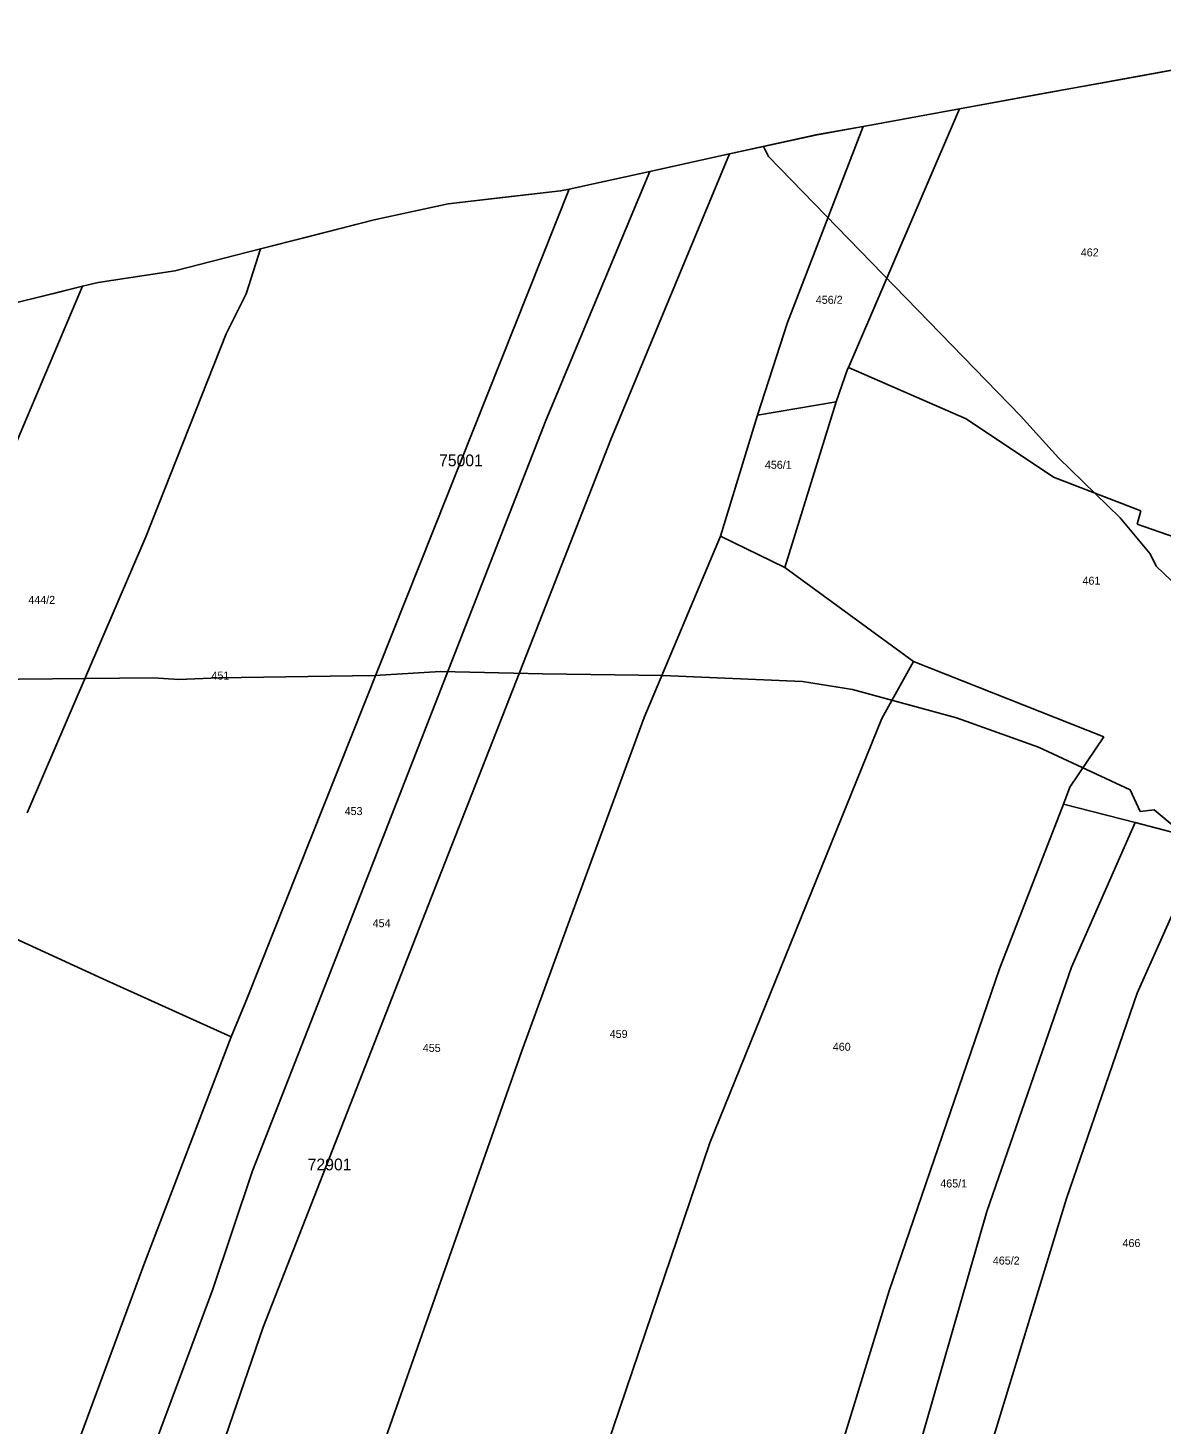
# Model space of a CAD drawing. Extents: x -743888 to -742027, y -1128394 to -1126768.
# Drawn here: x -742998.7 to -742758.2, y -1127090.1 to -1126793.6 of the extents above; entities that cross this region are included whole.
import ezdxf

# ---------------------------------------------------------------- set-up
doc = ezdxf.new("R2010")
doc.units = 0
for name, color, linetype in [('Vrstva 13', 7, 'Continuous'), ('Vrstva 18', 7, 'Continuous'), ('Vrstva 52', 7, 'Continuous'), ('Vrstva 53', 7, 'Continuous'), ('Vrstva 6', 7, 'Continuous')]:
    doc.layers.add(name, color=color, linetype=linetype)

msp = doc.modelspace()

# ---------------------------------------------------------------- linework, layer by layer
at = {"layer": 'Vrstva 13'}
for points in [[(-742769.01, -1126804.93), (-742735.24, -1126798.77)], [(-742800.98, -1126810.76), (-742782.52, -1126807.39)], [(-742782.52, -1126807.39), (-742769.01, -1126804.93)], [(-742821.45, -1126814.49), (-742800.98, -1126810.76)], [(-742849.79, -1126820.34), (-742831.12, -1126816.25)], [(-742831.12, -1126816.25), (-742821.45, -1126814.49)], [(-742859.97, -1126822.57), (-742849.79, -1126820.34)], [(-742883.83, -1126827.8), (-742866.72, -1126824.05)], [(-742866.72, -1126824.05), (-742859.97, -1126822.57)], [(-742897.44, -1126829.55), (-742885.68, -1126828.21)], [(-742885.68, -1126828.21), (-742883.83, -1126827.8)], [(-742925.21, -1126834.34), (-742909.52, -1126830.92)], [(-742909.52, -1126830.92), (-742897.44, -1126829.55)], [(-742939.84, -1126838.09), (-742925.21, -1126834.34)], [(-742949.34, -1126840.52), (-742939.84, -1126838.09)], [(-742967.54, -1126845.19), (-742949.34, -1126840.52)], [(-742983.82, -1126847.62), (-742967.54, -1126845.19)], [(-742992.38, -1126849.75), (-742987.15, -1126848.45)], [(-742987.15, -1126848.45), (-742983.82, -1126847.62)], [(-743014.97, -1126855.23), (-742997.62, -1126851.06)], [(-742997.62, -1126851.06), (-742992.38, -1126849.75)]]:
    msp.add_lwpolyline(points, dxfattribs=at)
at = {"layer": 'Vrstva 52'}
for points in [[(-742842.63, -1126818.77), (-742831.23, -1126816.27), (-742821.45, -1126814.49), (-742800.98, -1126810.76), (-742706.72, -1126793.58)], [(-743014.97, -1126855.23), (-742997.62, -1126851.06), (-742987.15, -1126848.45), (-742983.82, -1126847.62), (-742967.54, -1126845.19), (-742949.34, -1126840.52), (-742925.21, -1126834.34), (-742909.52, -1126830.92), (-742885.68, -1126828.21), (-742883.83, -1126827.8), (-742866.72, -1126824.05), (-742849.79, -1126820.34), (-742842.63, -1126818.77)], [(-742842.63, -1126818.77), (-742841.5, -1126820.88), (-742788.06, -1126876), (-742780, -1126884.88), (-742766.88, -1126897.63), (-742760.5, -1126905.25), (-742759.25, -1126907.88), (-742728.25, -1126937.5)], [(-743062.18, -1126930.43), (-743007.81, -1126932), (-742972.19, -1126931.63), (-742966.69, -1126932), (-742958.19, -1126931.63), (-742925.13, -1126931.13), (-742911.13, -1126930.25), (-742889.44, -1126930.75), (-742864, -1126931.13), (-742834.31, -1126932.38), (-742823.69, -1126934.13), (-742801.63, -1126940.13), (-742784.25, -1126946.38), (-742764.75, -1126955.38), (-742762.63, -1126960), (-742759.63, -1126959.63), (-742751.19, -1126966.75), (-742748.56, -1126970.88), (-742745.84, -1126975.32)]]:
    msp.add_lwpolyline(points, dxfattribs=at)
at = {"layer": 'Vrstva 6'}
for points in [[(-742824.58, -1126865.74), (-742800.98, -1126810.76)], [(-742837.53, -1126856.16), (-742821.45, -1126814.49)], [(-742875.03, -1126881.03), (-742849.79, -1126820.34)], [(-742888.83, -1126876.94), (-742866.72, -1126824.05)], [(-742933.06, -1126951.45), (-742883.83, -1126827.8)], [(-742952.43, -1126850.05), (-742949.34, -1126840.52)], [(-743003.48, -1126887.11), (-742987.15, -1126848.45)], [(-742956.68, -1126858.57), (-742952.43, -1126850.05)], [(-742843.85, -1126875.84), (-742837.53, -1126856.16)], [(-742973.7, -1126901.64), (-742956.68, -1126858.57)], [(-742827.15, -1126873), (-742824.73, -1126866.08)], [(-742824.73, -1126866.08), (-742824.58, -1126865.74)], [(-742824.58, -1126865.74), (-742799.57, -1126876.62)], [(-742843.85, -1126875.84), (-742827.15, -1126873)], [(-742838.1, -1126908.15), (-742827.15, -1126873)], [(-742935.17, -1126995.67), (-742888.83, -1126876.94)], [(-742851.71, -1126901.51), (-742843.85, -1126875.84)], [(-742799.57, -1126876.62), (-742781.04, -1126889)], [(-742891.52, -1126923.09), (-742875.03, -1126881.03)], [(-742781.04, -1126889), (-742762.5, -1126896.14)], [(-742763.27, -1126898.97), (-742762.5, -1126896.14)], [(-742763.27, -1126898.97), (-742750.49, -1126903.46)], [(-742998.88, -1126960.31), (-742973.7, -1126901.64)], [(-742867.91, -1126940.04), (-742851.71, -1126901.51)], [(-742851.71, -1126901.51), (-742838.1, -1126908.15)], [(-742838.1, -1126908.15), (-742810.76, -1126928.12)], [(-742913.81, -1126980), (-742891.52, -1126923.09)], [(-742817.51, -1126940.24), (-742810.76, -1126928.12)], [(-742810.76, -1126928.12), (-742770.36, -1126944.15)], [(-742884.2, -1126984.32), (-742867.91, -1126940.04)], [(-742854.01, -1127030.4), (-742817.51, -1126940.24)], [(-742777.55, -1126954.82), (-742770.36, -1126944.15)], [(-742952.5, -1127000.35), (-742933.06, -1126951.45)], [(-742778.92, -1126958.45), (-742777.55, -1126954.82)], [(-742792.49, -1126993.43), (-742778.92, -1126958.45)], [(-742778.92, -1126958.45), (-742763.72, -1126962.33)], [(-742777.21, -1126993.06), (-742763.72, -1126962.33)], [(-742763.72, -1126962.33), (-742748.81, -1126966.24)], [(-742763.25, -1126998.63), (-742748.81, -1126966.24)], [(-742948.78, -1127069.51), (-742913.81, -1126980)], [(-743011.05, -1126982.56), (-742982.82, -1126995.58)], [(-742894, -1127011.08), (-742884.2, -1126984.32)], [(-742815.95, -1127061.82), (-742792.49, -1126993.43)], [(-742795.18, -1127045), (-742777.21, -1126993.06)], [(-742982.82, -1126995.58), (-742955.58, -1127007.86)], [(-742951.08, -1127036.33), (-742935.17, -1126995.67)], [(-742778.25, -1127042.21), (-742763.25, -1126998.63)], [(-742955.58, -1127007.86), (-742952.5, -1127000.35)], [(-742973.91, -1127055.72), (-742955.58, -1127007.86)], [(-742935.81, -1127130.03), (-742894, -1127011.08)], [(-742891, -1127139.53), (-742854.01, -1127030.4)], [(-742959.53, -1127061.71), (-742951.08, -1127036.33)], [(-742813.25, -1127156.61), (-742778.25, -1127042.21)], [(-742812.1, -1127103.89), (-742795.18, -1127045)], [(-742988.72, -1127095.72), (-742973.91, -1127055.72)], [(-742981.52, -1127120.42), (-742959.53, -1127061.71)], [(-742842.98, -1127149.74), (-742815.95, -1127061.82)], [(-742967.31, -1127123.32), (-742948.78, -1127069.51)]]:
    msp.add_lwpolyline(points, dxfattribs=at)

# ---------------------------------------------------------------- texts
at = {"layer": 'Vrstva 18'}
for s, p in [('462', (-742775.24, -1126842.11)), ('456/2', (-742831.49, -1126852.18)), ('456/1', (-742842.3, -1126887.22)), ('461', (-742774.87, -1126911.83)), ('444/2', (-742998.66, -1126915.91)), ('451', (-742959.78, -1126931.98)), ('453', (-742931.51, -1126960.77)), ('454', (-742925.56, -1126984.58)), ('459', (-742875.24, -1127008.1)), ('460', (-742827.88, -1127010.83)), ('455', (-742914.92, -1127011.08)), ('465/1', (-742805.07, -1127039.87)), ('466', (-742766.38, -1127052.52)), ('465/2', (-742793.91, -1127056.24))]:
    msp.add_text(s, height=1.7, dxfattribs=at).set_placement(p)
at = {"layer": 'Vrstva 53'}
for s, p in [('75001', (-742911.47, -1126886.68)), ('72901', (-742939.36, -1127036.23))]:
    msp.add_text(s, height=2.5, dxfattribs=at).set_placement(p)

doc.saveas('drawing.dxf')
